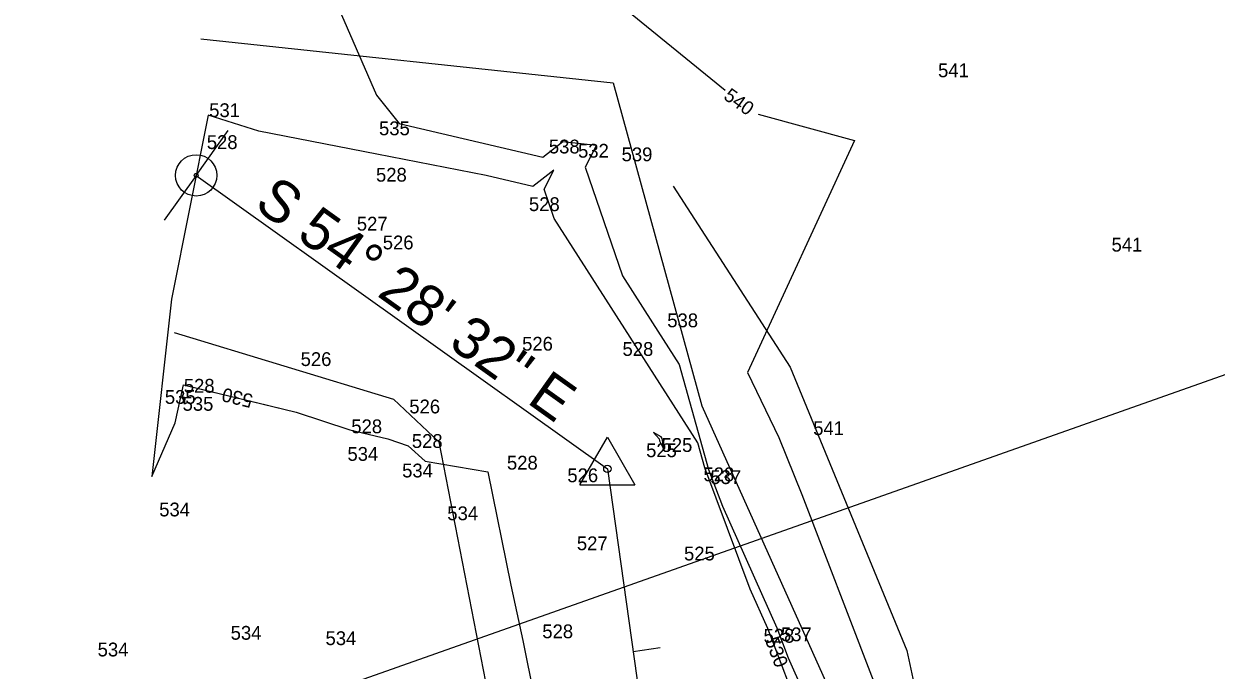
# Model space of a CAD drawing. Extents: x 1787461 to 1970323, y 938412 to 1118748.
# Drawn here: x 1967825.5 to 1967998.4, y 1118307.8 to 1118401.6 of the extents above; entities that cross this region are included whole.
import ezdxf

# ---------------------------------------------------------------- set-up
doc = ezdxf.new("R2010")
doc.units = 0
for name, color, linetype in [('Default', 7, 'Continuous'), ('Level 1', 7, 'Continuous'), ('RD_EX_DV_Prop', 7, 'Continuous'), ('RD_EX_Fence_Other', 7, 'Continuous'), ('RD_EX_H2O', 7, 'Continuous'), ('RD_HC_CL', 7, 'Continuous'), ('RD_HC_Data', 7, 'Continuous'), ('RD_HC_Data_Tic', 7, 'Continuous'), ('RD_SMD_Locator', 7, 'Continuous')]:
    doc.layers.add(name, color=color, linetype=linetype)

msp = doc.modelspace()

# ---------------------------------------------------------------- linework, layer by layer
at = {"layer": 'Default'}
for points in [[(1967896.62, 1118443.13), (1967872.88, 1118442.53), (1967872.23, 1118438.64), (1967872.37, 1118438.31), (1967873.14, 1118437.34), (1967876.15, 1118433.56), (1967927.22, 1118391.94)], [(1967896.62, 1118443.13), (1967872.88, 1118442.53), (1967872.23, 1118438.64), (1967872.37, 1118438.31), (1967873.14, 1118437.34), (1967876.15, 1118433.56), (1967927.22, 1118391.94)], [(1967896.62, 1118443.13), (1967872.88, 1118442.53), (1967872.23, 1118438.64), (1967872.37, 1118438.31), (1967873.14, 1118437.34), (1967876.15, 1118433.56), (1967927.22, 1118391.94)], [(1967896.62, 1118443.13), (1967872.88, 1118442.53), (1967872.23, 1118438.64), (1967872.37, 1118438.31), (1967873.14, 1118437.34), (1967876.15, 1118433.56), (1967927.22, 1118391.94)], [(1967896.62, 1118443.13), (1967872.88, 1118442.53), (1967872.23, 1118438.64), (1967872.37, 1118438.31), (1967873.14, 1118437.34), (1967876.15, 1118433.56), (1967927.22, 1118391.94)], [(1967896.62, 1118443.13), (1967872.88, 1118442.53), (1967872.23, 1118438.64), (1967872.37, 1118438.31), (1967873.14, 1118437.34), (1967876.15, 1118433.56), (1967927.22, 1118391.94)], [(1967896.62, 1118443.13), (1967872.88, 1118442.53), (1967872.23, 1118438.64), (1967872.37, 1118438.31), (1967873.14, 1118437.34), (1967876.15, 1118433.56), (1967927.22, 1118391.94)], [(1967864.89, 1118426.41), (1967863.9, 1118420.55), (1967876.68, 1118391.21), (1967879.95, 1118387.09), (1967900.78, 1118382.22), (1967903.7, 1118384.48), (1967908.55, 1118383.95), (1967906.91, 1118380.79), (1967912.33, 1118365.02), (1967916.69, 1118358.2), (1967920.57, 1118352.14), (1967924.83, 1118336.92), (1967926.82, 1118331.61), (1967934.7, 1118313.97), (1967936.36, 1118309.6), (1967943.07, 1118294.53), (1967943.46, 1118288.03), (1967945.34, 1118269.57), (1967945.36, 1118269.24), (1967945.39, 1118269.15), (1967945.43, 1118269.12), (1967946.15, 1118267.14), (1967946.71, 1118265.53)], [(1967864.89, 1118426.41), (1967863.9, 1118420.55), (1967876.68, 1118391.21), (1967879.95, 1118387.09), (1967900.78, 1118382.22), (1967903.7, 1118384.48), (1967908.55, 1118383.95), (1967906.91, 1118380.79), (1967912.33, 1118365.02), (1967916.69, 1118358.2), (1967920.57, 1118352.14), (1967924.83, 1118336.92), (1967926.82, 1118331.61), (1967934.7, 1118313.97), (1967936.36, 1118309.6), (1967943.07, 1118294.53), (1967943.46, 1118288.03), (1967945.34, 1118269.57), (1967945.36, 1118269.24), (1967945.39, 1118269.15), (1967945.43, 1118269.12), (1967946.15, 1118267.14), (1967946.71, 1118265.53)], [(1967864.89, 1118426.41), (1967863.9, 1118420.55), (1967876.68, 1118391.21), (1967879.95, 1118387.09), (1967900.78, 1118382.22), (1967903.7, 1118384.48), (1967908.55, 1118383.95), (1967906.91, 1118380.79), (1967912.33, 1118365.02), (1967916.69, 1118358.2), (1967920.57, 1118352.14), (1967924.83, 1118336.92), (1967926.82, 1118331.61), (1967934.7, 1118313.97), (1967936.36, 1118309.6), (1967943.07, 1118294.53), (1967943.46, 1118288.03), (1967945.34, 1118269.57), (1967945.36, 1118269.24), (1967945.39, 1118269.15), (1967945.43, 1118269.12), (1967946.15, 1118267.14), (1967946.71, 1118265.53)], [(1967864.89, 1118426.41), (1967863.9, 1118420.55), (1967876.68, 1118391.21), (1967879.95, 1118387.09), (1967900.78, 1118382.22), (1967903.7, 1118384.48), (1967908.55, 1118383.95), (1967906.91, 1118380.79), (1967912.33, 1118365.02), (1967916.69, 1118358.2), (1967920.57, 1118352.14), (1967924.83, 1118336.92), (1967926.82, 1118331.61), (1967934.7, 1118313.97), (1967936.36, 1118309.6), (1967943.07, 1118294.53), (1967943.46, 1118288.03), (1967945.34, 1118269.57), (1967945.36, 1118269.24), (1967945.39, 1118269.15), (1967945.43, 1118269.12), (1967946.15, 1118267.14), (1967946.71, 1118265.53)], [(1967864.89, 1118426.41), (1967863.9, 1118420.55), (1967876.68, 1118391.21), (1967879.95, 1118387.09), (1967900.78, 1118382.22), (1967903.7, 1118384.48), (1967908.55, 1118383.95), (1967906.91, 1118380.79), (1967912.33, 1118365.02), (1967916.69, 1118358.2), (1967920.57, 1118352.14), (1967924.83, 1118336.92), (1967926.82, 1118331.61), (1967934.7, 1118313.97), (1967936.36, 1118309.6), (1967943.07, 1118294.53), (1967943.46, 1118288.03), (1967945.34, 1118269.57), (1967945.36, 1118269.24), (1967945.39, 1118269.15), (1967945.43, 1118269.12), (1967946.15, 1118267.14), (1967946.71, 1118265.53)], [(1967864.89, 1118426.41), (1967863.9, 1118420.55), (1967876.68, 1118391.21), (1967879.95, 1118387.09), (1967900.78, 1118382.22), (1967903.7, 1118384.48), (1967908.55, 1118383.95), (1967906.91, 1118380.79), (1967912.33, 1118365.02), (1967916.69, 1118358.2), (1967920.57, 1118352.14), (1967924.83, 1118336.92), (1967926.82, 1118331.61), (1967934.7, 1118313.97), (1967936.36, 1118309.6), (1967943.07, 1118294.53), (1967943.46, 1118288.03), (1967945.34, 1118269.57), (1967945.36, 1118269.24), (1967945.39, 1118269.15), (1967945.43, 1118269.12), (1967946.15, 1118267.14), (1967946.71, 1118265.53)], [(1967863.9, 1118420.55), (1967876.68, 1118391.21), (1967879.95, 1118387.09), (1967900.78, 1118382.22), (1967903.7, 1118384.48), (1967908.55, 1118383.95), (1967906.91, 1118380.79), (1967912.33, 1118365.02), (1967916.69, 1118358.2), (1967920.57, 1118352.14), (1967924.83, 1118336.92), (1967926.82, 1118331.61), (1967934.7, 1118313.97), (1967936.36, 1118309.6), (1967943.07, 1118294.53)], [(1967938.5, 1118300.51), (1967933.41, 1118313.86), (1967930.85, 1118319.59), (1967924.26, 1118337.16), (1967923.24, 1118340.81), (1967913.44, 1118356.11), (1967902.41, 1118373.35), (1967900.96, 1118377.58), (1967902.39, 1118380.35), (1967899.31, 1118377.97), (1967892.57, 1118379.55), (1967876.72, 1118382.66), (1967859.61, 1118386.02), (1967852.27, 1118388.31), (1967846.94, 1118361.65), (1967844.09, 1118335.92), (1967847.45, 1118343.69), (1967848.66, 1118349.21), (1967865, 1118345.26), (1967872.8, 1118342.69), (1967878.29, 1118341.36), (1967881.24, 1118340.37), (1967883.71, 1118338.15), (1967892.81, 1118336.57), (1967896.13, 1118320.15), (1967897.87, 1118312.12), (1967901.22, 1118295.55)], [(1967933.75, 1118312.96), (1967933.41, 1118313.86), (1967930.85, 1118319.59), (1967924.26, 1118337.16), (1967923.24, 1118340.81), (1967913.44, 1118356.11), (1967902.41, 1118373.35), (1967900.96, 1118377.58), (1967902.39, 1118380.35), (1967899.31, 1118377.97), (1967892.57, 1118379.55), (1967876.72, 1118382.66), (1967859.61, 1118386.02), (1967852.27, 1118388.31), (1967846.94, 1118361.65), (1967844.09, 1118335.92), (1967847.45, 1118343.69), (1967848.66, 1118349.21), (1967853.22, 1118348.11)], [(1967933.75, 1118312.96), (1967933.41, 1118313.86), (1967930.85, 1118319.59), (1967924.26, 1118337.16), (1967923.24, 1118340.81), (1967913.44, 1118356.11), (1967902.41, 1118373.35), (1967900.96, 1118377.58), (1967902.39, 1118380.35), (1967899.31, 1118377.97), (1967892.57, 1118379.55), (1967876.72, 1118382.66), (1967859.61, 1118386.02), (1967852.27, 1118388.31), (1967846.94, 1118361.65), (1967844.09, 1118335.92), (1967847.45, 1118343.69), (1967848.66, 1118349.21), (1967853.22, 1118348.11)], [(1967933.75, 1118312.96), (1967933.41, 1118313.86), (1967930.85, 1118319.59), (1967924.26, 1118337.16), (1967923.24, 1118340.81), (1967913.44, 1118356.11), (1967902.41, 1118373.35), (1967900.96, 1118377.58), (1967902.39, 1118380.35), (1967899.31, 1118377.97), (1967892.57, 1118379.55), (1967876.72, 1118382.66), (1967859.61, 1118386.02), (1967852.27, 1118388.31), (1967846.94, 1118361.65), (1967844.09, 1118335.92), (1967847.45, 1118343.69), (1967848.66, 1118349.21), (1967853.22, 1118348.11)], [(1967933.75, 1118312.96), (1967933.41, 1118313.86), (1967930.85, 1118319.59), (1967924.26, 1118337.16), (1967923.24, 1118340.81), (1967913.44, 1118356.11), (1967902.41, 1118373.35), (1967900.96, 1118377.58), (1967902.39, 1118380.35), (1967899.31, 1118377.97), (1967892.57, 1118379.55), (1967876.72, 1118382.66), (1967859.61, 1118386.02), (1967852.27, 1118388.31), (1967846.94, 1118361.65), (1967844.09, 1118335.92), (1967847.45, 1118343.69), (1967848.66, 1118349.21), (1967853.22, 1118348.11)], [(1967933.75, 1118312.96), (1967933.41, 1118313.86), (1967930.85, 1118319.59), (1967924.26, 1118337.16), (1967923.24, 1118340.81), (1967913.44, 1118356.11), (1967902.41, 1118373.35), (1967900.96, 1118377.58), (1967902.39, 1118380.35), (1967899.31, 1118377.97), (1967892.57, 1118379.55), (1967876.72, 1118382.66), (1967859.61, 1118386.02), (1967852.27, 1118388.31), (1967846.94, 1118361.65), (1967844.09, 1118335.92), (1967847.45, 1118343.69), (1967848.66, 1118349.21), (1967853.22, 1118348.11)], [(1967933.75, 1118312.96), (1967933.41, 1118313.86), (1967930.85, 1118319.59), (1967924.26, 1118337.16), (1967923.24, 1118340.81), (1967913.44, 1118356.11), (1967902.41, 1118373.35), (1967900.96, 1118377.58), (1967902.39, 1118380.35), (1967899.31, 1118377.97), (1967892.57, 1118379.55), (1967876.72, 1118382.66), (1967859.61, 1118386.02), (1967852.27, 1118388.31), (1967846.94, 1118361.65), (1967844.09, 1118335.92), (1967847.45, 1118343.69), (1967848.66, 1118349.21), (1967853.22, 1118348.11)], [(1967932.03, 1118388.47), (1967945.98, 1118384.64), (1967930.44, 1118350.98), (1967935.02, 1118341.55), (1967938.33, 1118333.31), (1967948.45, 1118307.02), (1967948.8, 1118306.16)], [(1967932.03, 1118388.47), (1967945.98, 1118384.64), (1967930.44, 1118350.98), (1967935.02, 1118341.55), (1967938.33, 1118333.31), (1967948.45, 1118307.02), (1967948.8, 1118306.16)], [(1967932.03, 1118388.47), (1967945.98, 1118384.64), (1967930.44, 1118350.98), (1967935.02, 1118341.55), (1967938.33, 1118333.31), (1967948.45, 1118307.02), (1967948.8, 1118306.16)], [(1967932.03, 1118388.47), (1967945.98, 1118384.64), (1967930.44, 1118350.98), (1967935.02, 1118341.55), (1967938.33, 1118333.31), (1967948.45, 1118307.02), (1967948.8, 1118306.16)], [(1967932.03, 1118388.47), (1967945.98, 1118384.64), (1967930.44, 1118350.98), (1967935.02, 1118341.55), (1967938.33, 1118333.31), (1967948.45, 1118307.02), (1967948.8, 1118306.16)], [(1967932.03, 1118388.47), (1967945.98, 1118384.64), (1967930.44, 1118350.98), (1967935.02, 1118341.55), (1967938.33, 1118333.31), (1967948.45, 1118307.02), (1967948.8, 1118306.16)], [(1967932.03, 1118388.47), (1967945.98, 1118384.64), (1967930.44, 1118350.98), (1967935.02, 1118341.55), (1967938.33, 1118333.31), (1967948.45, 1118307.02), (1967948.8, 1118306.16)], [(1967848.54, 1118347.45), (1967848.48, 1118347.18), (1967848.8, 1118347.37), (1967848.58, 1118347.45), (1967848.54, 1118347.45)], [(1967848.54, 1118347.45), (1967848.48, 1118347.18), (1967848.8, 1118347.37), (1967848.58, 1118347.45), (1967848.54, 1118347.45)], [(1967848.54, 1118347.45), (1967848.48, 1118347.18), (1967848.8, 1118347.37), (1967848.58, 1118347.45), (1967848.54, 1118347.45)], [(1967848.54, 1118347.45), (1967848.48, 1118347.18), (1967848.8, 1118347.37), (1967848.58, 1118347.45), (1967848.54, 1118347.45)], [(1967848.54, 1118347.45), (1967848.48, 1118347.18), (1967848.8, 1118347.37), (1967848.58, 1118347.45), (1967848.54, 1118347.45)], [(1967848.54, 1118347.45), (1967848.48, 1118347.18), (1967848.8, 1118347.37), (1967848.58, 1118347.45), (1967848.54, 1118347.45)], [(1967848.54, 1118347.45), (1967848.48, 1118347.18), (1967848.8, 1118347.37), (1967848.58, 1118347.45), (1967848.54, 1118347.45)], [(1967859.06, 1118346.7), (1967865, 1118345.26), (1967872.8, 1118342.69), (1967878.29, 1118341.36), (1967881.24, 1118340.37), (1967883.71, 1118338.15), (1967892.81, 1118336.57), (1967896.13, 1118320.15), (1967897.87, 1118312.12), (1967901.22, 1118295.55), (1967902.9, 1118287.77), (1967903.97, 1118282.51), (1967905.46, 1118274.74), (1967906.33, 1118257.73), (1967906.82, 1118248.29), (1967906.47, 1118243.26), (1967906.86, 1118243.21), (1967906.88, 1118243.2), (1967907.2, 1118240.66), (1967908.91, 1118233.03), (1967909.01, 1118232.49), (1967910.98, 1118222.44), (1967913.74, 1118207.95)], [(1967859.06, 1118346.7), (1967865, 1118345.26), (1967872.8, 1118342.69), (1967878.29, 1118341.36), (1967881.24, 1118340.37), (1967883.71, 1118338.15), (1967892.81, 1118336.57), (1967896.13, 1118320.15), (1967897.87, 1118312.12), (1967901.22, 1118295.55), (1967902.9, 1118287.77), (1967903.97, 1118282.51), (1967905.46, 1118274.74), (1967906.33, 1118257.73), (1967906.82, 1118248.29), (1967906.47, 1118243.26), (1967906.86, 1118243.21), (1967906.88, 1118243.2), (1967907.2, 1118240.66), (1967908.91, 1118233.03), (1967909.01, 1118232.49), (1967910.98, 1118222.44), (1967913.74, 1118207.95)], [(1967859.06, 1118346.7), (1967865, 1118345.26), (1967872.8, 1118342.69), (1967878.29, 1118341.36), (1967881.24, 1118340.37), (1967883.71, 1118338.15), (1967892.81, 1118336.57), (1967896.13, 1118320.15), (1967897.87, 1118312.12), (1967901.22, 1118295.55), (1967902.9, 1118287.77), (1967903.97, 1118282.51), (1967905.46, 1118274.74), (1967906.33, 1118257.73), (1967906.82, 1118248.29), (1967906.47, 1118243.26), (1967906.86, 1118243.21), (1967906.88, 1118243.2), (1967907.2, 1118240.66), (1967908.91, 1118233.03), (1967909.01, 1118232.49), (1967910.98, 1118222.44), (1967913.74, 1118207.95)], [(1967859.06, 1118346.7), (1967865, 1118345.26), (1967872.8, 1118342.69), (1967878.29, 1118341.36), (1967881.24, 1118340.37), (1967883.71, 1118338.15), (1967892.81, 1118336.57), (1967896.13, 1118320.15), (1967897.87, 1118312.12), (1967901.22, 1118295.55), (1967902.9, 1118287.77), (1967903.97, 1118282.51), (1967905.46, 1118274.74), (1967906.33, 1118257.73), (1967906.82, 1118248.29), (1967906.47, 1118243.26), (1967906.86, 1118243.21), (1967906.88, 1118243.2), (1967907.2, 1118240.66), (1967908.91, 1118233.03), (1967909.01, 1118232.49), (1967910.98, 1118222.44), (1967913.74, 1118207.95)], [(1967859.06, 1118346.7), (1967865, 1118345.26), (1967872.8, 1118342.69), (1967878.29, 1118341.36), (1967881.24, 1118340.37), (1967883.71, 1118338.15), (1967892.81, 1118336.57), (1967896.13, 1118320.15), (1967897.87, 1118312.12), (1967901.22, 1118295.55), (1967902.9, 1118287.77), (1967903.97, 1118282.51), (1967905.46, 1118274.74), (1967906.33, 1118257.73), (1967906.82, 1118248.29), (1967906.47, 1118243.26), (1967906.86, 1118243.21), (1967906.88, 1118243.2), (1967907.2, 1118240.66), (1967908.91, 1118233.03), (1967909.01, 1118232.49), (1967910.98, 1118222.44), (1967913.74, 1118207.95)], [(1967859.06, 1118346.7), (1967865, 1118345.26), (1967872.8, 1118342.69), (1967878.29, 1118341.36), (1967881.24, 1118340.37), (1967883.71, 1118338.15), (1967892.81, 1118336.57), (1967896.13, 1118320.15), (1967897.87, 1118312.12), (1967901.22, 1118295.55), (1967902.9, 1118287.77), (1967903.97, 1118282.51), (1967905.46, 1118274.74), (1967906.33, 1118257.73), (1967906.82, 1118248.29), (1967906.47, 1118243.26), (1967906.86, 1118243.21), (1967906.88, 1118243.2), (1967907.2, 1118240.66), (1967908.91, 1118233.03), (1967909.01, 1118232.49), (1967910.98, 1118222.44), (1967913.74, 1118207.95)], [(1967918.37, 1118339.72), (1967918.07, 1118341.43), (1967917.93, 1118341.66), (1967916.85, 1118342.32), (1967917.63, 1118341.36), (1967917.68, 1118341.11), (1967918.37, 1118339.72)], [(1967918.37, 1118339.72), (1967918.07, 1118341.43), (1967917.93, 1118341.66), (1967916.85, 1118342.32), (1967917.63, 1118341.36), (1967917.68, 1118341.11), (1967918.37, 1118339.72)], [(1967918.37, 1118339.72), (1967918.07, 1118341.43), (1967917.93, 1118341.66), (1967916.85, 1118342.32), (1967917.63, 1118341.36), (1967917.68, 1118341.11), (1967918.37, 1118339.72)], [(1967918.37, 1118339.72), (1967918.07, 1118341.43), (1967917.93, 1118341.66), (1967916.85, 1118342.32), (1967917.63, 1118341.36), (1967917.68, 1118341.11), (1967918.37, 1118339.72)], [(1967918.37, 1118339.72), (1967918.07, 1118341.43), (1967917.93, 1118341.66), (1967916.85, 1118342.32), (1967917.63, 1118341.36), (1967917.68, 1118341.11), (1967918.37, 1118339.72)], [(1967918.37, 1118339.72), (1967918.07, 1118341.43), (1967917.93, 1118341.66), (1967916.85, 1118342.32), (1967917.63, 1118341.36), (1967917.68, 1118341.11), (1967918.37, 1118339.72)], [(1967918.37, 1118339.72), (1967918.07, 1118341.43), (1967917.93, 1118341.66), (1967916.85, 1118342.32), (1967917.63, 1118341.36), (1967917.68, 1118341.11), (1967918.37, 1118339.72)]]:
    msp.add_lwpolyline(points, dxfattribs=at)
at = {"layer": 'Level 1'}
msp.add_line((1968062.38, 1118372.81), (1967713.43, 1118249.52), dxfattribs=at)
at = {"layer": 'RD_EX_DV_Prop'}
for p, q in [((1967850.51, 1118379.59), (1967910.14, 1118337.02)), ((1967910.14, 1118337.02), (1967929.83, 1118196.9))]:
    msp.add_line(p, q, dxfattribs=at)
at = {"layer": 'RD_EX_Fence_Other'}
msp.add_lwpolyline([(1967919.7, 1118378.02), (1967936.64, 1118351.76), (1967953.58, 1118310.67), (1967964.44, 1118259.92), (1967962.38, 1118197.45), (1967934.48, 1118153.92), (1967925.2, 1118115.74), (1967925.02, 1118060.61), (1967940.38, 1118016.99), (1967944.7, 1118004.73)], dxfattribs=at)
at = {"layer": 'RD_EX_H2O'}
for points in [[(1967851.18, 1118399.4), (1967910.98, 1118393), (1967923.85, 1118346.18), (1967942.91, 1118303.76), (1967945.44, 1118252.51), (1967960.35, 1118200.64), (1967921.61, 1118157.98), (1967878.95, 1118126.47), (1967857.49, 1118083), (1967842.73, 1118040.05), (1967828.54, 1117994.01), (1967828.4, 1117944.09), (1967833.42, 1117912.71)], [(1967847.31, 1118356.81), (1967879.15, 1118347.14), (1967885.7, 1118340.94), (1967895.17, 1118292.21), (1967905.1, 1118241.75), (1967913.15, 1118203.17), (1967903.06, 1118190.95), (1967846.3, 1118148.6), (1967822.76, 1118102.41), (1967798.93, 1118056.05), (1967790.6, 1118001.77), (1967788.7, 1117944.97), (1967797.09, 1117898.55), (1967795.44, 1117890.32)]]:
    msp.add_lwpolyline(points, dxfattribs=at)
at = {"layer": 'RD_HC_CL'}
for p, q in [((1967850.51, 1118379.59), (1967910.14, 1118337.02)), ((1967910.14, 1118337.02), (1967929.83, 1118196.9))]:
    msp.add_line(p, q, dxfattribs=at)
at = {"layer": 'RD_HC_Data'}
for p, q in [((1967906.17, 1118334.73), (1967910.14, 1118341.61)), ((1967910.14, 1118341.61), (1967914.11, 1118334.73)), ((1967906.17, 1118334.73), (1967914.11, 1118334.73))]:
    msp.add_line(p, q, dxfattribs=at)
for centre, radius in [((1967850.51, 1118379.59), 3), ((1967850.51, 1118379.59), 0.282), ((1967910.14, 1118337.02), 0.529)]:
    msp.add_circle(centre, radius, dxfattribs=at)
at = {"layer": 'RD_HC_Data_Tic'}
for p, q in [((1967850.51, 1118379.59), (1967855.16, 1118386.1)), ((1967850.51, 1118379.59), (1967845.86, 1118373.08)), ((1967913.86, 1118310.55), (1967917.82, 1118311.1))]:
    msp.add_line(p, q, dxfattribs=at)
at = {"layer": 'RD_SMD_Locator'}
for centre in [(1967850.51, 1118379.59), (1967910.14, 1118337.02)]:
    msp.add_circle(centre, 0.001, dxfattribs=at)

# ---------------------------------------------------------------- texts
at = {"layer": 'Default'}
for s, p in [('541', (1967958.1, 1118393.83)), ('531', (1967852.4, 1118388.04)), ('535', (1967877.03, 1118385.41)), ('528', (1967852.05, 1118383.41)), ('538', (1967901.66, 1118382.77)), ('532', (1967905.89, 1118382.16)), ('539', (1967912.21, 1118381.64)), ('528', (1967876.59, 1118378.68)), ('528', (1967898.77, 1118374.41)), ('527', (1967873.81, 1118371.58)), ('526', (1967877.57, 1118368.86)), ('541', (1967983.26, 1118368.54)), ('538', (1967918.83, 1118357.56)), ('526', (1967897.78, 1118354.17)), ('528', (1967912.34, 1118353.41)), ('526', (1967865.66, 1118351.94)), ('535', (1967845.97, 1118346.45)), ('535', (1967845.97, 1118346.45)), ('535', (1967845.97, 1118346.45)), ('535', (1967845.97, 1118346.45)), ('535', (1967845.97, 1118346.45)), ('535', (1967845.97, 1118346.45)), ('528', (1967848.72, 1118348.07)), ('535', (1967848.54, 1118345.45)), ('526', (1967881.42, 1118345.07)), ('528', (1967873.01, 1118342.19)), ('541', (1967939.99, 1118341.92)), ('528', (1967881.79, 1118340.06)), ('534', (1967872.45, 1118338.19)), ('525', (1967915.76, 1118338.72)), ('525', (1967915.76, 1118338.72)), ('525', (1967915.76, 1118338.72)), ('525', (1967915.76, 1118338.72)), ('525', (1967915.76, 1118338.72)), ('525', (1967915.76, 1118338.72)), ('525', (1967918, 1118339.48)), ('528', (1967895.58, 1118336.92)), ('534', (1967880.38, 1118335.78)), ('526', (1967904.34, 1118335.09)), ('528', (1967924.08, 1118335.23)), ('537', (1967925.08, 1118334.82)), ('534', (1967845.15, 1118330.13)), ('534', (1967886.93, 1118329.58)), ('527', (1967905.72, 1118325.23)), ('525', (1967921.26, 1118323.74)), ('534', (1967855.51, 1118312.24)), ('528', (1967900.71, 1118312.46)), ('537', (1967935.32, 1118312.02)), ('534', (1967869.27, 1118311.46)), ('528', (1967932.79, 1118311.81)), ('534', (1967836.22, 1118309.82))]:
    msp.add_text(s, height=2, dxfattribs=at).set_placement(p)
for s, rotation, p in [('540', 324.1439, (1967926.85, 1118390.77)), ('540', 324.1439, (1967926.85, 1118390.77)), ('540', 324.1439, (1967926.85, 1118390.77)), ('540', 324.1439, (1967926.85, 1118390.77)), ('540', 324.1439, (1967926.85, 1118390.77)), ('540', 324.1439, (1967926.85, 1118390.77)), ('540', 324.1439, (1967926.85, 1118390.77)), ('530', 166.3914, (1967858.88, 1118347.77)), ('530', 166.3914, (1967858.88, 1118347.77)), ('530', 166.3914, (1967858.88, 1118347.77)), ('530', 166.3914, (1967858.88, 1118347.77)), ('530', 166.3914, (1967858.88, 1118347.77)), ('530', 166.3914, (1967858.88, 1118347.77)), ('530', 290.8687, (1967932.97, 1118312.2)), ('530', 290.8687, (1967932.97, 1118312.2)), ('530', 290.8687, (1967932.97, 1118312.2)), ('530', 290.8687, (1967932.97, 1118312.2)), ('530', 290.8687, (1967932.97, 1118312.2)), ('530', 290.8687, (1967932.97, 1118312.2))]:
    msp.add_text(s, height=2, rotation=rotation, dxfattribs=at).set_placement(p)
at = {"layer": 'RD_HC_Data'}
msp.add_text('S 54%%d 28\' 32" E', height=6, rotation=324.4755, dxfattribs=at).set_placement((1967858.73, 1118374.95))

doc.saveas('drawing.dxf')
